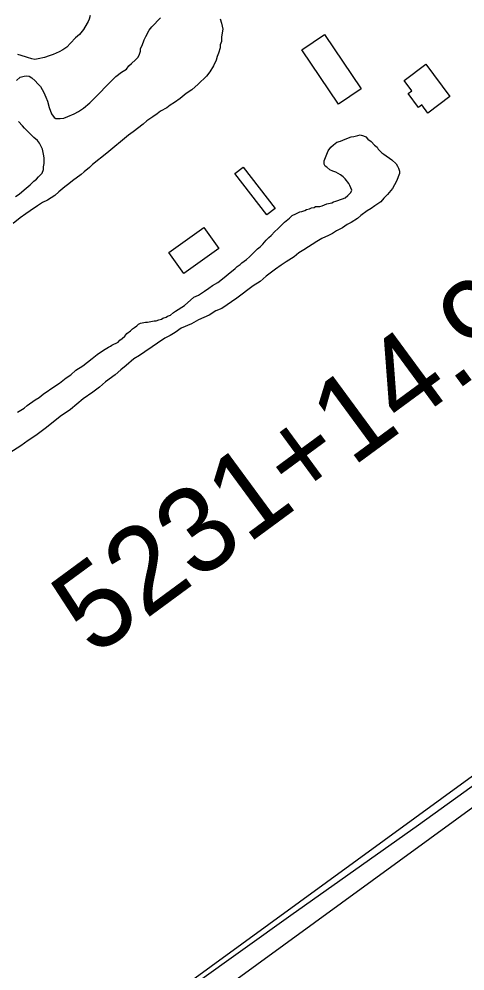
# Model space of a CAD drawing. Extents: x 3324125 to 3362000, y 600753 to 626151.
# Drawn here: x 3332206 to 3332729, y 613099 to 614214 of the extents above; entities that cross this region are included whole.
import ezdxf

# ---------------------------------------------------------------- set-up
doc = ezdxf.new("R2010")
doc.units = 0
for name, color, linetype in [('V-BLDG-OTLN', 7, 'Continuous'), ('V-ROAD-CNTR', 7, 'Continuous'), ('V-SITE-VEGE', 7, 'Continuous'), ('V-SURV-IDEN', 7, 'Continuous'), ('V-TOPO-SHOR', 7, 'Continuous')]:
    doc.layers.add(name, color=color, linetype=linetype)

msp = doc.modelspace()

# ---------------------------------------------------------------- linework, layer by layer
at = {"layer": 'V-BLDG-OTLN'}
for points in [[(3332580.4, 614113.8), (3332537.4, 614177.6), (3332564.1, 614195.7), (3332607.2, 614131.9)], [(3332682.6, 614160.7), (3332711, 614122.8), (3332685.1, 614103.4), (3332678, 614113), (3332674.2, 614110.1), (3332662, 614126.3), (3332666.4, 614129.6), (3332657.3, 614141.7)], [(3332496.3, 613984.4), (3332459.1, 614032.7), (3332468.9, 614040.2), (3332506.1, 613991.9)], [(3332381.7, 613940), (3332422.5, 613969.3), (3332440.1, 613944.7), (3332399.3, 613915.4)]]:
    msp.add_lwpolyline(points, close=True, dxfattribs=at)
at = {"layer": 'V-ROAD-CNTR'}
for points in [[(3332218.1, 612948.7), (3332296.1, 613005.9), (3333210.5, 613671.6)], [(3332241.4, 612928.5), (3332313.8, 612981.7), (3333228.1, 613647.4)]]:
    msp.add_lwpolyline(points, dxfattribs=at)
at = {"layer": 'V-SITE-VEGE'}
for points in [[(3332441.7, 614213.8), (3332443.5, 614209), (3332444.7, 614201.8), (3332443.5, 614192.9), (3332443.5, 614187.5), (3332441.7, 614183.3), (3332441.7, 614179.8), (3332440, 614173.8), (3332438.2, 614169.6), (3332437, 614165.4), (3332434, 614158.8), (3332429.8, 614151.7), (3332425.7, 614146.9), (3332416.1, 614137.3), (3332408.4, 614130.8), (3332401.8, 614126.6), (3332394.7, 614120.6), (3332388.1, 614115.8), (3332383.3, 614112.8), (3332379.2, 614109.8), (3332372, 614105.6), (3332367.8, 614102.6), (3332363, 614099.1), (3332355.9, 614094.3), (3332351.7, 614090.7), (3332339.8, 614081.7), (3332334.4, 614077.5), (3332308.8, 614056.6), (3332292.1, 614043.4), (3332288.5, 614039.9), (3332282.5, 614034.5), (3332279, 614031.5), (3332268.8, 614024.3), (3332264.6, 614020.7), (3332259.9, 614017.1), (3332252.7, 614011.2), (3332248, 614007), (3332239.6, 614001.6), (3332233.6, 613998.6), (3332227.7, 613995), (3332219.3, 613989), (3332214, 613985.4), (3332207.4, 613980.7), (3332199, 613974.1)], [(3332289.5, 614217.8), (3332288.3, 614213.6), (3332287.1, 614210.6), (3332285.9, 614208.8), (3332281.7, 614201.6), (3332277, 614195.7), (3332272.2, 614191.5), (3332266.2, 614185.5), (3332262, 614180.7), (3332257.3, 614177.7), (3332253.1, 614175.3), (3332245.9, 614172.3), (3332241.2, 614170.5), (3332235.8, 614168.7), (3332228.6, 614166.9), (3332224.5, 614166.3), (3332220.9, 614166.9), (3332216.1, 614168.7), (3332213.7, 614169.3), (3332204.8, 614172.3)], [(3332326, 614151.5), (3332331.9, 614155.1), (3332334.9, 614158.7), (3332337.9, 614161.7), (3332342.7, 614165.9), (3332345.6, 614168.9), (3332347.4, 614172.5), (3332348.6, 614176.1), (3332348.6, 614179), (3332350.4, 614182.6), (3332352.8, 614189.2), (3332354.6, 614193.4), (3332358.7, 614200.5), (3332361.7, 614204.7), (3332371.8, 614214.9)], [(3332203, 614141.8), (3332207.2, 614145.4), (3332211.9, 614146.6), (3332214.9, 614147.2), (3332217.9, 614146.6), (3332220.9, 614144.8), (3332225.1, 614141.3), (3332228.1, 614137.7), (3332231.1, 614134.7), (3332235.3, 614127.5), (3332237.6, 614122.2), (3332239.4, 614117.4), (3332241.2, 614110.2), (3332244.2, 614102.5), (3332247.2, 614098.3), (3332249, 614097.1), (3332254.4, 614097.1), (3332258.6, 614097.7), (3332263.3, 614099.5), (3332270.5, 614102.5), (3332275.9, 614105.5), (3332281.8, 614109.1), (3332289, 614115.7), (3332319.4, 614146.2), (3332326, 614151.5)], [(3332202, 614005.7), (3332206.2, 614008.7), (3332212.1, 614013.5), (3332219.3, 614019.5), (3332223.5, 614023.7), (3332226.4, 614026), (3332228.8, 614029), (3332233, 614033.2), (3332234.8, 614037.4), (3332234.8, 614040.4), (3332235.4, 614044.6), (3332235.4, 614051.1), (3332234.8, 614055.3), (3332233.6, 614061.3), (3332230, 614068.4), (3332227.6, 614071.4), (3332223.4, 614075), (3332212.6, 614085.7), (3332210.2, 614088.7), (3332205.5, 614093.5)], [(3332297.7, 613820.8), (3332304.9, 613825.6), (3332309.1, 613828), (3332310.9, 613829.2), (3332313.3, 613830.4), (3332315, 613831.6), (3332322.2, 613835.1), (3332324, 613837.5), (3332327, 613839.3), (3332330, 613842.3), (3332332.3, 613845.3), (3332336.5, 613848.3), (3332338.9, 613850.7), (3332341.3, 613852.5), (3332344.3, 613854.3), (3332346.1, 613856.1), (3332348.4, 613857.3), (3332354.4, 613858.5), (3332356.8, 613858.5), (3332364.6, 613860.3), (3332366.9, 613860.3), (3332369.9, 613861.5), (3332372.9, 613862.1), (3332374.7, 613863.3), (3332378.3, 613864.5), (3332380.1, 613865.7), (3332383.7, 613866.9), (3332387.2, 613869.8), (3332389.6, 613871.6), (3332399.8, 613878.2), (3332411.1, 613887.8), (3332416.5, 613890.2), (3332423.6, 613895), (3332428.4, 613898.6), (3332432.6, 613901.6), (3332439.1, 613905.1), (3332446.3, 613911.1), (3332451, 613914.7), (3332459.4, 613921.3), (3332461.8, 613923.7), (3332465.4, 613926.1), (3332467.1, 613927.9), (3332472.5, 613932), (3332476.1, 613935), (3332481.5, 613940.4), (3332485.6, 613944.6), (3332488.6, 613947), (3332491.6, 613950), (3332495.8, 613954.8), (3332498.7, 613957.8), (3332501.7, 613960.1), (3332505.9, 613964.9), (3332509.5, 613967.9), (3332517.2, 613975.7), (3332523.2, 613980.5), (3332526.2, 613983.5), (3332530.3, 613985.3), (3332535.1, 613987.7), (3332537.5, 613988.3), (3332541.1, 613989.4), (3332542.9, 613990.6), (3332546.5, 613991.2), (3332548.8, 613992.4), (3332551.8, 613993), (3332553.6, 613994.2), (3332558.4, 613994.2), (3332561.4, 613994.8), (3332566.8, 613997.2), (3332572.7, 613998.4), (3332574.5, 613999.6), (3332577.5, 614000.2), (3332585.2, 614003.2), (3332588.2, 614004.4), (3332591.2, 614006.8), (3332594.8, 614010.4), (3332596, 614013.4), (3332593.6, 614018.8), (3332592.4, 614021.2), (3332588.2, 614026.5), (3332585.8, 614028.9), (3332582.8, 614031.3), (3332577.4, 614034.3), (3332573.9, 614035.5), (3332570.3, 614037.2), (3332566.7, 614040.2), (3332564.9, 614041.4), (3332563.7, 614043.8), (3332563.7, 614047.4), (3332568.5, 614059.3), (3332571.4, 614063.5), (3332574.4, 614066.5), (3332578.6, 614069.5), (3332582.8, 614070.7), (3332588.1, 614073.1), (3332595.3, 614075.5), (3332598.3, 614076.1), (3332603.1, 614077.3), (3332606, 614077.9), (3332609.6, 614076.7), (3332612.6, 614075.5), (3332615, 614073.1)], [(3332615, 614073.1), (3332618.6, 614070.1), (3332622.8, 614066), (3332625.8, 614063.6), (3332627, 614061.2), (3332631.1, 614057), (3332633.5, 614055.2), (3332636.5, 614053.5), (3332640.1, 614050.5), (3332643.1, 614048.7), (3332647.9, 614043.9), (3332649.7, 614041.5), (3332650.9, 614039.1), (3332652.1, 614035.6), (3332652.1, 614032.6), (3332648.5, 614023.6), (3332643.7, 614015.3), (3332637.8, 614008.1), (3332633.6, 614003.9), (3332630, 613999.7), (3332622.9, 613994.9), (3332618.7, 613991.9), (3332613.9, 613988.9), (3332606.8, 613983.6), (3332602.6, 613980), (3332595.4, 613975.2), (3332590.7, 613972.8), (3332585.3, 613969.2), (3332578.1, 613965.6), (3332573.4, 613962.6), (3332568.6, 613960.2), (3332560.8, 613956.6), (3332554.9, 613953.1), (3332540, 613943.5), (3332534, 613939.9), (3332528.6, 613935.1), (3332519.1, 613929.1), (3332513.1, 613925.5), (3332506.6, 613920.8), (3332495.8, 613912.4), (3332488.7, 613906.4), (3332480.3, 613901), (3332461.2, 613886.7), (3332443.9, 613874.7), (3332436.8, 613871.7), (3332429, 613866.9), (3332416.5, 613861.5), (3332408.1, 613856.7), (3332396.2, 613851.4), (3332389, 613846.6), (3332383.1, 613843), (3332377.1, 613840), (3332368.2, 613834), (3332362.2, 613829.8), (3332353.3, 613823.8), (3332347.3, 613819.7), (3332340.7, 613815.5), (3332331.8, 613807.7), (3332325.2, 613802.9), (3332318.7, 613796.9), (3332307.3, 613788.6), (3332300.2, 613782.6), (3332292.4, 613776.6), (3332281.1, 613768.8), (3332266.2, 613756.3), (3332254.3, 613747.9), (3332238.2, 613735.3), (3332225.6, 613725.8), (3332216.7, 613719.8), (3332208.3, 613713.8), (3332195.2, 613705.4)], [(3332204.1, 613753.2), (3332211.9, 613758), (3332215.4, 613761), (3332225, 613767.6), (3332229.8, 613770.5), (3332234.5, 613774.1), (3332248.2, 613783.7), (3332253.6, 613787.3), (3332261.4, 613793.3), (3332266.7, 613796.9), (3332272.7, 613802.2), (3332281, 613807.6), (3332291.8, 613816), (3332297.7, 613820.8)]]:
    msp.add_lwpolyline(points, dxfattribs=at)
at = {"layer": 'V-TOPO-SHOR'}
msp.add_lwpolyline([(3332797.4, 613358.2), (3332674.2, 613269.5), (3332524.4, 613163.7), (3332302.5, 613004.7), (3332225, 612948)], dxfattribs=at)

# ---------------------------------------------------------------- texts
at = {"layer": 'V-SURV-IDEN'}
msp.add_text('5231+14.9', height=100, rotation=36.32, dxfattribs=at).set_placement((3332293.9, 613465.7))

doc.saveas('drawing.dxf')
